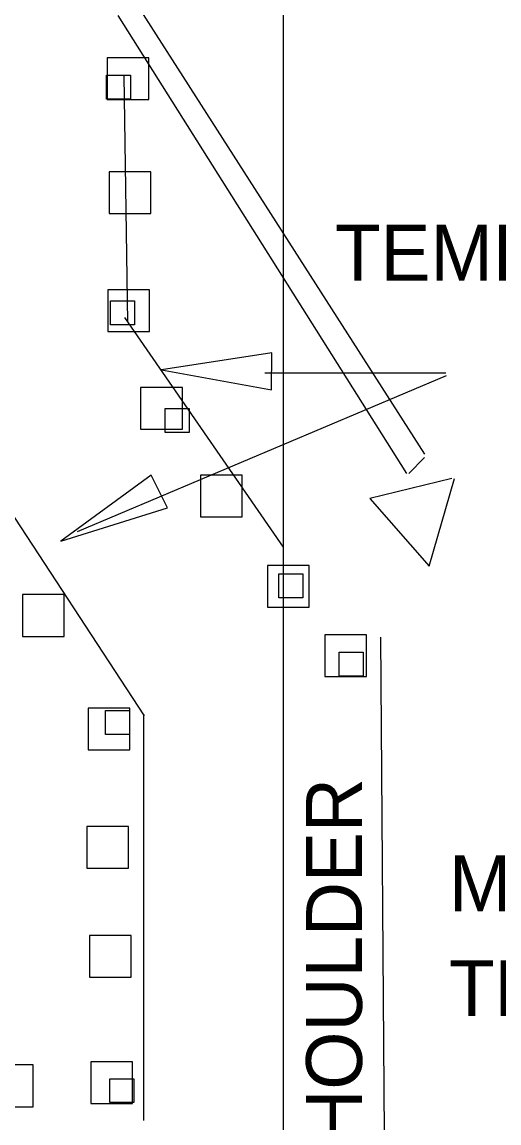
# Model space of a CAD drawing. Extents: x 1531.4 to 1538.6, y 1529.6 to 1539.6.
# Drawn here: x 1535.745 to 1536.256, y 1533.633 to 1534.815 of the extents above; entities that cross this region are included whole.
import ezdxf

# ---------------------------------------------------------------- set-up
doc = ezdxf.new("R2010")
doc.units = 0
for name, color, linetype in [('DETL-DIMS', 7, 'Continuous'), ('DETL-LINE', 7, 'Continuous'), ('DETL-NOTE', 7, 'Continuous'), ('USER-BORD', 7, 'Continuous')]:
    doc.layers.add(name, color=color, linetype=linetype)

# ---------------------------------------------------------------- blocks, each defined once
blk = doc.blocks.new('CD1')
at = {"layer": 'USER-BORD'}
blk.add_lwpolyline([(0, 0.0312), (0.0312, 0.0312), (0.0312, 0), (0, 0)], close=True, dxfattribs=at)

msp = doc.modelspace()

# ---------------------------------------------------------------- linework, layer by layer
at = {"layer": 'DETL-DIMS'}
for p, q in [((1536.005, 1534.4384), (1536.1992, 1534.4384)), ((1535.8042, 1534.2681), (1536.2, 1534.4354))]:
    msp.add_line(p, q, dxfattribs=at)
for points in [[(1536.0122, 1534.4203), (1536.0128, 1534.4597), (1535.8941, 1534.4417)], [(1535.9008, 1534.2934), (1535.883, 1534.3286), (1535.7863, 1534.2578)]]:
    msp.add_lwpolyline(points, close=True, dxfattribs=at)
at = {"layer": 'DETL-LINE'}
for p, q in [((1536.0249, 1535.6524), (1536.0249, 1534.3818)), ((1535.8712, 1534.828), (1536.1764, 1534.3511)), ((1535.8475, 1534.8218), (1536.1572, 1534.3304)), ((1535.854, 1534.757), (1535.8579, 1534.4927)), ((1535.8545, 1534.4976), (1536.0249, 1534.2513)), ((1535.876, 1534.0703), (1535.6735, 1534.3794)), ((1536.0249, 1534.3825), (1536.0249, 1533.6241)), ((1536.1763, 1534.3474), (1536.1596, 1534.3303)), ((1536.2058, 1534.325), (1536.1177, 1534.3037)), ((1536.1815, 1534.2308), (1536.2088, 1534.325)), ((1536.1177, 1534.3037), (1536.1815, 1534.2308)), ((1536.1336, 1533.6219), (1536.1296, 1534.1548)), ((1535.8752, 1533.6362), (1535.8752, 1534.072))]:
    msp.add_line(p, q, dxfattribs=at)
for points in [[(1535.8358, 1534.7316), (1535.8806, 1534.7316), (1535.8806, 1534.7764), (1535.8358, 1534.7764)], [(1535.8381, 1534.6094), (1535.8829, 1534.6094), (1535.8829, 1534.6542), (1535.8381, 1534.6542)], [(1535.8366, 1534.4826), (1535.8814, 1534.4826), (1535.8814, 1534.5274), (1535.8366, 1534.5274)], [(1535.8719, 1534.378), (1535.9167, 1534.378), (1535.9167, 1534.4228), (1535.8719, 1534.4228)], [(1535.936, 1534.2838), (1535.9808, 1534.2838), (1535.9808, 1534.3286), (1535.936, 1534.3286)], [(1536.0079, 1534.187), (1536.0527, 1534.187), (1536.0527, 1534.2318), (1536.0079, 1534.2318)], [(1535.745, 1534.1556), (1535.7898, 1534.1556), (1535.7898, 1534.2004), (1535.745, 1534.2004)], [(1536.0694, 1534.1124), (1536.1142, 1534.1124), (1536.1142, 1534.1572), (1536.0694, 1534.1572)], [(1535.8156, 1534.0339), (1535.8604, 1534.0339), (1535.8604, 1534.0787), (1535.8156, 1534.0787)], [(1535.8142, 1533.9068), (1535.859, 1533.9068), (1535.859, 1533.9516), (1535.8142, 1533.9516)], [(1535.817, 1533.7898), (1535.8618, 1533.7898), (1535.8618, 1533.8346), (1535.817, 1533.8346)], [(1535.7116, 1533.6509), (1535.7564, 1533.6509), (1535.7564, 1533.6957), (1535.7116, 1533.6957)], [(1535.8184, 1533.6542), (1535.8632, 1533.6542), (1535.8632, 1533.699), (1535.8184, 1533.699)]]:
    msp.add_lwpolyline(points, close=True, dxfattribs=at)

# ---------------------------------------------------------------- block references
at = {"layer": 'DETL-LINE', "xscale": 0.820627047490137, "yscale": 0.820627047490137}
for p in [(1535.8354, 1534.7322), (1535.8396, 1534.49), (1535.8982, 1534.3744), (1536.0203, 1534.197), (1536.0849, 1534.1129), (1535.8343, 1534.0503), (1535.8389, 1533.6553)]:
    msp.add_blockref('CD1', p, dxfattribs=at)

# ---------------------------------------------------------------- texts
at = {"layer": 'DETL-NOTE'}
for s, p in [('TEMPORARY STRIPING (TYP.)', (1536.0803, 1534.5372)), ('MOVEABLE BARRIER', (1536.2027, 1533.8605)), ('TRANSFER VEHICLE', (1536.2027, 1533.7481))]:
    msp.add_text(s, height=0.06, dxfattribs=at).set_placement(p)
msp.add_text('SHOULDER', height=0.06, rotation=90, dxfattribs=at).set_placement((1536.1094, 1533.5577))

doc.saveas('drawing.dxf')
